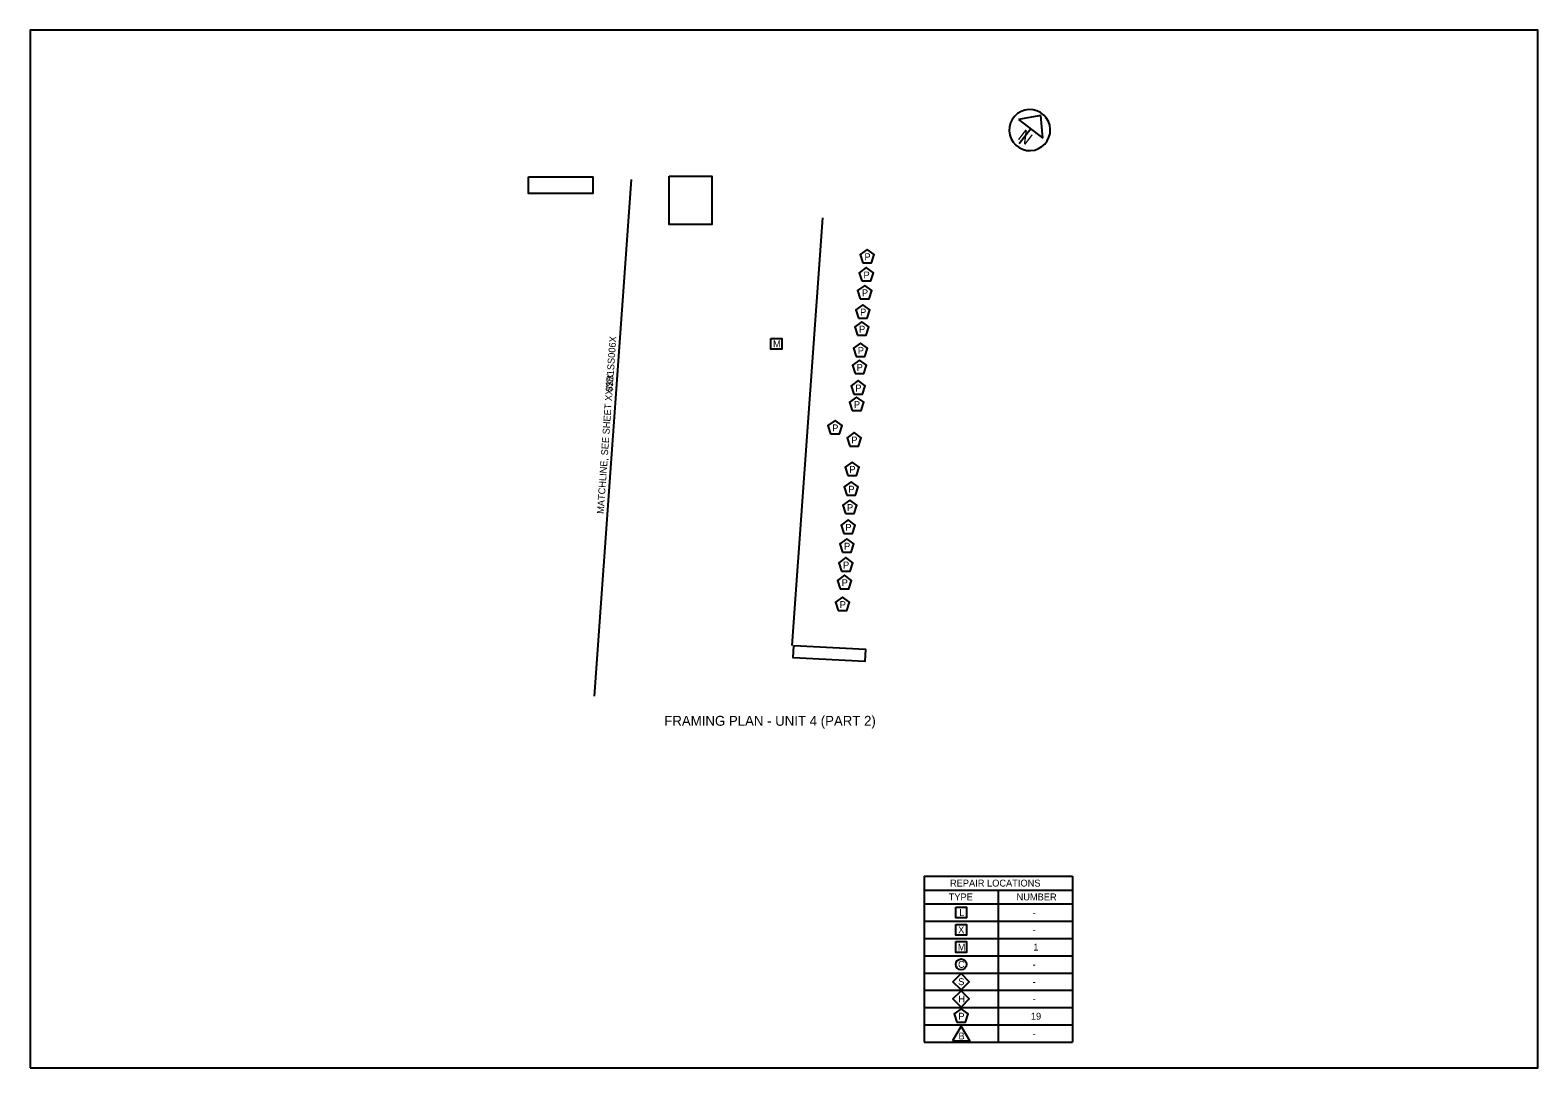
# Model space of a CAD drawing. Extents: x 100 to 130.5, y 100 to 121.
import ezdxf

# ---------------------------------------------------------------- set-up
doc = ezdxf.new("R2010")
doc.units = 0
for name, color, linetype in [('BR_P_Gen_Text', 7, 'Continuous'), ('BR_X_Sub_Centerline', 7, 'Continuous'), ('BR_X_Sub_Text', 7, 'Continuous'), ('SC_Scratch1', 7, 'Continuous'), ('SH_Data', 7, 'Continuous'), ('SH_Masking', 7, 'Continuous')]:
    doc.layers.add(name, color=color, linetype=linetype)

msp = doc.modelspace()

# ---------------------------------------------------------------- linework, layer by layer
at = {"layer": 'BR_P_Gen_Text'}
for p, q in [((112.16, 117.977), (111.407, 107.523)), ((118.083, 103.879), (118.083, 100.519)), ((118.083, 103.879), (121.083, 103.879)), ((121.083, 103.879), (121.083, 100.519)), ((118.083, 103.599), (121.083, 103.599)), ((119.583, 103.599), (119.583, 100.519)), ((118.083, 103.319), (121.083, 103.319)), ((118.083, 102.969), (121.083, 102.969)), ((118.083, 102.619), (121.083, 102.619)), ((118.083, 102.269), (121.083, 102.269)), ((118.083, 101.919), (121.083, 101.919)), ((118.083, 101.569), (121.083, 101.569)), ((118.083, 101.219), (121.083, 101.219)), ((118.083, 100.869), (121.083, 100.869)), ((118.083, 100.519), (121.083, 100.519))]:
    msp.add_line(p, q, dxfattribs=at)
for points in [[(116.845, 116.292), (117.022, 116.292), (117.076, 116.46), (116.934, 116.563), (116.791, 116.46)], [(116.827, 115.924), (117.004, 115.924), (117.058, 116.091), (116.915, 116.195), (116.773, 116.091)], [(116.794, 115.563), (116.971, 115.563), (117.025, 115.73), (116.883, 115.834), (116.74, 115.73)], [(116.758, 115.173), (116.934, 115.173), (116.989, 115.34), (116.846, 115.444), (116.703, 115.34)], [(116.736, 114.826), (116.912, 114.826), (116.967, 114.994), (116.824, 115.098), (116.682, 114.994)], [(114.986, 114.763), (115.206, 114.763), (115.206, 114.543), (114.986, 114.543)], [(116.711, 114.396), (116.887, 114.396), (116.941, 114.564), (116.799, 114.667), (116.656, 114.564)], [(116.687, 114.053), (116.864, 114.053), (116.918, 114.22), (116.775, 114.324), (116.633, 114.22)], [(116.661, 113.635), (116.837, 113.635), (116.892, 113.803), (116.749, 113.907), (116.607, 113.803)], [(116.632, 113.303), (116.808, 113.303), (116.863, 113.471), (116.72, 113.574), (116.577, 113.471)], [(116.194, 112.829), (116.371, 112.829), (116.425, 112.997), (116.282, 113.1), (116.14, 112.997)], [(116.579, 112.583), (116.755, 112.583), (116.81, 112.751), (116.667, 112.855), (116.525, 112.751)], [(116.541, 111.989), (116.718, 111.989), (116.772, 112.156), (116.629, 112.26), (116.487, 112.156)], [(116.52, 111.587), (116.697, 111.587), (116.751, 111.755), (116.609, 111.859), (116.466, 111.755)], [(116.492, 111.216), (116.669, 111.216), (116.723, 111.384), (116.581, 111.488), (116.438, 111.384)], [(116.46, 110.816), (116.636, 110.816), (116.691, 110.984), (116.548, 111.088), (116.406, 110.984)], [(116.433, 110.434), (116.61, 110.434), (116.664, 110.602), (116.521, 110.705), (116.379, 110.602)], [(116.412, 110.054), (116.589, 110.054), (116.643, 110.221), (116.5, 110.325), (116.358, 110.221)], [(116.384, 109.697), (116.561, 109.697), (116.615, 109.864), (116.472, 109.968), (116.33, 109.864)], [(116.345, 109.253), (116.521, 109.253), (116.575, 109.421), (116.433, 109.525), (116.29, 109.421)], [(118.723, 103.254), (118.943, 103.254), (118.943, 103.034), (118.723, 103.034)], [(118.723, 102.904), (118.943, 102.904), (118.943, 102.684), (118.723, 102.684)], [(118.723, 102.554), (118.943, 102.554), (118.943, 102.334), (118.723, 102.334)], [(118.833, 101.909), (118.998, 101.744), (118.833, 101.579), (118.668, 101.744)], [(118.833, 101.559), (118.998, 101.394), (118.833, 101.229), (118.668, 101.394)], [(118.745, 100.923), (118.922, 100.923), (118.976, 101.091), (118.833, 101.194), (118.691, 101.091)], [(118.66, 100.544), (119.007, 100.544), (118.833, 100.844)]]:
    msp.add_lwpolyline(points, close=True, dxfattribs=at)
msp.add_circle((118.833, 102.094), 0.11, dxfattribs=at)
at = {"layer": 'BR_X_Sub_Centerline'}
msp.add_line((115.418, 108.545), (116.033, 117.204), dxfattribs=at)
at = {"layer": 'BR_X_Sub_Text'}
msp.add_lwpolyline([(115.451, 108.55), (116.9, 108.475), (116.886, 108.221), (115.438, 108.297)], close=True, dxfattribs=at)
at = {"layer": 'SC_Scratch1'}
msp.add_lwpolyline([(100, 100), (130.5, 100), (130.5, 121), (100, 121)], close=True, dxfattribs=at)
at = {"layer": 'SH_Data'}
for p, q in [((120.449, 119.274), (119.997, 119.19)), ((120.486, 118.816), (120.449, 119.274)), ((119.997, 119.19), (120.486, 118.816)), ((120.241, 119.003), (120.006, 118.696))]:
    msp.add_line(p, q, dxfattribs=at)
msp.add_arc((120.222, 118.977), 0.415, 92.3383, 92.3218, dxfattribs=at)
at = {"layer": 'SH_Masking'}
for points in [[(112.924, 118.047), (113.793, 118.047), (113.793, 117.064), (112.924, 117.064)], [(110.084, 118.032), (111.38, 118.032), (111.38, 117.691), (110.084, 117.691)]]:
    msp.add_lwpolyline(points, close=True, dxfattribs=at)

# ---------------------------------------------------------------- texts
at = {"layer": 'BR_P_Gen_Text'}
for s, height, p in [('P', 0.14, (116.877, 116.343)), ('P', 0.14, (116.859, 115.975)), ('P', 0.14, (116.826, 115.614)), ('P', 0.14, (116.79, 115.224)), ('P', 0.14, (116.768, 114.878)), ('M', 0.14, (115.028, 114.583)), ('P', 0.14, (116.743, 114.447)), ('P', 0.14, (116.719, 114.104)), ('P', 0.14, (116.693, 113.687)), ('P', 0.14, (116.664, 113.354)), ('P', 0.14, (116.226, 112.88)), ('P', 0.14, (116.611, 112.635)), ('P', 0.14, (116.573, 112.04)), ('P', 0.14, (116.552, 111.639)), ('P', 0.14, (116.524, 111.268)), ('P', 0.14, (116.492, 110.868)), ('P', 0.14, (116.465, 110.485)), ('P', 0.14, (116.444, 110.105)), ('P', 0.14, (116.416, 109.748)), ('P', 0.14, (116.377, 109.305)), ('FRAMING PLAN - UNIT 4 (PART 2)', 0.2, (112.828, 106.923)), ('REPAIR LOCATIONS', 0.14, (118.608, 103.669)), ('TYPE', 0.14, (118.582, 103.389)), ('NUMBER', 0.14, (119.955, 103.389)), ('L', 0.14, (118.795, 103.074)), ('-', 0.14, (120.28, 103.074)), ('X', 0.14, (118.773, 102.724)), ('-', 0.14, (120.28, 102.724)), ('M', 0.14, (118.765, 102.374)), ('1', 0.14, (120.294, 102.374)), ('C', 0.14, (118.771, 102.024)), ('-', 0.14, (120.28, 102.024)), ('S', 0.14, (118.775, 101.674)), ('-', 0.14, (120.28, 101.674)), ('H', 0.14, (118.777, 101.324)), ('-', 0.14, (120.28, 101.324)), ('P', 0.14, (118.777, 100.974)), ('19', 0.14, (120.244, 100.974)), ('B', 0.14, (118.779, 100.574)), ('-', 0.14, (120.28, 100.624))]:
    msp.add_text(s, height=height, dxfattribs=at).set_placement(p)
for s, p in [('$$B1SS006X', (111.78, 113.679)), ('MATCHLINE, SEE SHEET XX/XX', (111.602, 111.207))]:
    msp.add_text(s, height=0.14, rotation=85.8808, dxfattribs=at).set_placement(p)
at = {"layer": 'SH_Data'}
msp.add_text('N', height=0.25, rotation=322.5585, dxfattribs=at).set_placement((119.962, 118.809))

doc.saveas('drawing.dxf')
